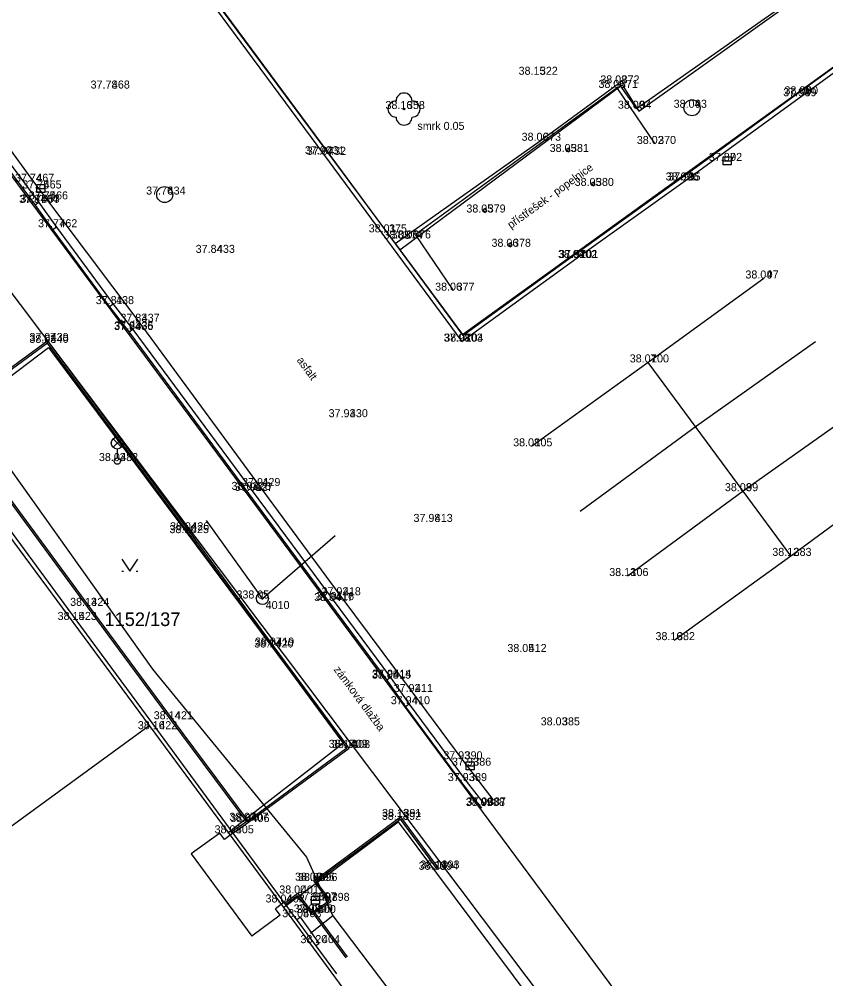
# Model space of a CAD drawing. Extents: x -609709 to -609357, y -1051535 to -1051131.
# Drawn here: x -609555.38 to -609530.2, y -1051361.09 to -1051331.13 of the extents above; entities that cross this region are included whole.
import ezdxf

# ---------------------------------------------------------------- set-up
doc = ezdxf.new("R2010")
doc.units = 0
for name, color, linetype in [('Vrstva 1', 7, 'Continuous'), ('Vrstva 10', 7, 'Continuous'), ('Vrstva 12', 7, 'Continuous'), ('Vrstva 18', 7, 'Continuous'), ('Vrstva 2', 7, 'Continuous'), ('Vrstva 3', 7, 'Continuous'), ('Vrstva 4', 7, 'Continuous'), ('Vrstva 5', 7, 'Continuous'), ('Vrstva 7', 7, 'Continuous'), ('Vrstva 9', 7, 'Continuous')]:
    doc.layers.add(name, color=color, linetype=linetype)

msp = doc.modelspace()

# ---------------------------------------------------------------- linework, layer by layer
at = {"layer": 'Vrstva 1'}
for p, q in [((-609539.22, -1051332.87), (-609539.22, -1051332.87)), ((-609552.58, -1051333.3), (-609552.58, -1051333.3)), ((-609536.72, -1051333.28), (-609536.72, -1051333.28)), ((-609536.67, -1051333.14), (-609536.67, -1051333.14)), ((-609530.96, -1051333.54), (-609530.96, -1051333.54)), ((-609530.91, -1051333.48), (-609530.91, -1051333.48)), ((-609534.38, -1051333.9), (-609534.38, -1051333.9)), ((-609543.37, -1051333.94), (-609543.37, -1051333.94)), ((-609536.11, -1051333.93), (-609536.11, -1051333.93)), ((-609539.12, -1051334.93), (-609539.12, -1051334.93)), ((-609535.53, -1051335.03), (-609535.53, -1051335.03)), ((-609545.88, -1051335.35), (-609545.88, -1051335.35)), ((-609545.83, -1051335.37), (-609545.83, -1051335.37)), ((-609538.25, -1051335.28), (-609538.25, -1051335.28)), ((-609533.28, -1051335.56), (-609533.28, -1051335.56)), ((-609554.94, -1051336.21), (-609554.94, -1051336.21)), ((-609534.63, -1051336.17), (-609534.63, -1051336.17)), ((-609534.58, -1051336.17), (-609534.58, -1051336.17)), ((-609554.71, -1051336.42), (-609554.71, -1051336.42)), ((-609550.84, -1051336.61), (-609550.84, -1051336.61)), ((-609537.47, -1051336.34), (-609537.47, -1051336.34)), ((-609554.81, -1051336.87), (-609554.81, -1051336.87)), ((-609554.77, -1051336.86), (-609554.77, -1051336.86)), ((-609554.51, -1051336.76), (-609554.51, -1051336.76)), ((-609540.85, -1051337.17), (-609540.85, -1051337.17)), ((-609554.22, -1051337.63), (-609554.22, -1051337.63)), ((-609543.93, -1051337.79), (-609543.93, -1051337.79)), ((-609543.44, -1051337.99), (-609543.44, -1051337.99)), ((-609543.18, -1051337.98), (-609543.18, -1051337.98)), ((-609540.06, -1051338.24), (-609540.06, -1051338.24)), ((-609549.3, -1051338.43), (-609549.3, -1051338.43)), ((-609537.99, -1051338.59), (-609537.99, -1051338.59)), ((-609537.96, -1051338.59), (-609537.96, -1051338.59)), ((-609532.14, -1051339.23), (-609532.14, -1051339.23)), ((-609541.82, -1051339.61), (-609541.82, -1051339.61)), ((-609552.45, -1051340.03), (-609552.45, -1051340.03)), ((-609551.65, -1051340.58), (-609551.65, -1051340.58)), ((-609551.85, -1051340.84), (-609551.85, -1051340.84)), ((-609551.84, -1051340.82), (-609551.84, -1051340.82)), ((-609554.49, -1051341.18), (-609554.49, -1051341.18)), ((-609554.49, -1051341.24), (-609554.49, -1051341.24)), ((-609541.56, -1051341.2), (-609541.56, -1051341.2)), ((-609541.54, -1051341.2), (-609541.54, -1051341.2)), ((-609535.75, -1051341.85), (-609535.75, -1051341.85)), ((-609545.15, -1051343.56), (-609545.15, -1051343.56)), ((-609539.39, -1051344.47), (-609539.39, -1051344.47)), ((-609552.32, -1051344.93), (-609552.32, -1051344.93)), ((-609548.18, -1051345.83), (-609548.18, -1051345.83)), ((-609548.11, -1051345.86), (-609548.11, -1051345.86)), ((-609547.88, -1051345.71), (-609547.88, -1051345.71)), ((-609532.78, -1051345.87), (-609532.78, -1051345.87)), ((-609550.1, -1051347.09), (-609550.1, -1051347.09)), ((-609542.5, -1051346.83), (-609542.5, -1051346.83)), ((-609550.11, -1051347.18), (-609550.11, -1051347.18)), ((-609531.3, -1051347.89), (-609531.3, -1051347.89)), ((-609536.39, -1051348.52), (-609536.39, -1051348.52)), ((-609545.37, -1051349.12), (-609545.37, -1051349.12)), ((-609553.22, -1051349.45), (-609553.22, -1051349.45)), ((-609547.79, -1051349.22), (-609547.79, -1051349.22)), ((-609545.6, -1051349.3), (-609545.6, -1051349.3)), ((-609545.58, -1051349.27), (-609545.58, -1051349.27)), ((-609553.61, -1051349.89), (-609553.61, -1051349.89)), ((-609547.45, -1051350.69), (-609547.45, -1051350.69)), ((-609534.94, -1051350.52), (-609534.94, -1051350.52)), ((-609547.47, -1051350.75), (-609547.47, -1051350.75)), ((-609539.57, -1051350.89), (-609539.57, -1051350.89)), ((-609543.8, -1051351.72), (-609543.8, -1051351.72)), ((-609543.79, -1051351.69), (-609543.79, -1051351.69)), ((-609543.12, -1051352.14), (-609543.12, -1051352.14)), ((-609543.21, -1051352.52), (-609543.21, -1051352.52)), ((-609550.61, -1051352.99), (-609550.61, -1051352.99)), ((-609551.1, -1051353.3), (-609551.1, -1051353.3)), ((-609538.53, -1051353.18), (-609538.53, -1051353.18)), ((-609545.15, -1051353.88), (-609545.15, -1051353.88)), ((-609545.08, -1051353.89), (-609545.08, -1051353.89)), ((-609541.57, -1051354.24), (-609541.57, -1051354.24)), ((-609541.3, -1051354.44), (-609541.3, -1051354.44)), ((-609541.43, -1051354.92), (-609541.43, -1051354.92)), ((-609540.87, -1051355.7), (-609540.87, -1051355.7)), ((-609540.84, -1051355.68), (-609540.84, -1051355.68)), ((-609543.48, -1051356.04), (-609543.48, -1051356.04)), ((-609548.25, -1051356.16), (-609548.25, -1051356.16)), ((-609548.22, -1051356.2), (-609548.22, -1051356.2)), ((-609543.49, -1051356.13), (-609543.49, -1051356.13)), ((-609548.71, -1051356.55), (-609548.71, -1051356.55)), ((-609542.33, -1051357.69), (-609542.33, -1051357.69)), ((-609542.29, -1051357.65), (-609542.29, -1051357.65)), ((-609546.19, -1051358.03), (-609546.19, -1051358.03)), ((-609546.1, -1051358.04), (-609546.1, -1051358.04)), ((-609546.68, -1051358.43), (-609546.68, -1051358.43)), ((-609547.12, -1051358.71), (-609547.12, -1051358.71)), ((-609546.13, -1051358.64), (-609546.13, -1051358.64)), ((-609545.72, -1051358.66), (-609545.72, -1051358.66)), ((-609546.24, -1051359.02), (-609546.24, -1051359.02)), ((-609546.15, -1051359.04), (-609546.15, -1051359.04)), ((-609546.6, -1051359.17), (-609546.6, -1051359.17)), ((-609546.02, -1051359.98), (-609546.02, -1051359.98))]:
    msp.add_line(p, q, dxfattribs=at)
at = {"layer": 'Vrstva 10'}
for p, q in [((-609581.79, -1051300.71), (-609506.66, -1051402.14)), ((-609567.21, -1051306.38), (-609543.5, -1051338.34)), ((-609541.54, -1051340.98), (-609507.4, -1051316.31)), ((-609536.04, -1051334.01), (-609523.24, -1051324.85)), ((-609543.5, -1051338.34), (-609536.56, -1051333.18)), ((-609536.56, -1051333.18), (-609536.04, -1051334.01)), ((-609543.5, -1051338.34), (-609541.54, -1051340.98)), ((-609558.05, -1051344.09), (-609554.47, -1051341.38)), ((-609554.47, -1051341.38), (-609545.26, -1051353.73)), ((-609558.05, -1051344.09), (-609551.33, -1051353.19)), ((-609552.18, -1051347.995), (-609551.93, -1051348.37)), ((-609551.93, -1051348.37), (-609551.68, -1051347.995)), ((-609552.18, -1051348.37), (-609552.13, -1051348.37)), ((-609551.73, -1051348.37), (-609551.68, -1051348.37)), ((-609560.47, -1051359.86), (-609551.33, -1051353.19)), ((-609551.33, -1051353.19), (-609548.86, -1051356.53)), ((-609548.86, -1051356.53), (-609545.26, -1051353.73)), ((-609547.13, -1051358.87), (-609543.55, -1051356.19)), ((-609543.55, -1051356.19), (-609530.27, -1051373.99)), ((-609548.86, -1051356.53), (-609547.13, -1051358.87)), ((-609547.13, -1051358.87), (-609540.48, -1051367.88))]:
    msp.add_line(p, q, dxfattribs=at)
at = {"layer": 'Vrstva 12'}
for points in [[(-609615.546, -1051325.052), (-609614.108, -1051326.974), (-609589.099, -1051308.266), (-609582.815, -1051303.565), (-609514.844, -1051393.856), (-609499.807, -1051382.785), (-609467.693, -1051377.467)], [(-609556.47, -1051344.07), (-609551.22, -1051351.43), (-609546.41, -1051357.3), (-609545.59, -1051359.13), (-609546.284, -1051359.683)], [(-609545.59, -1051359.13), (-609538.86, -1051368.03), (-609535.11, -1051373.63), (-609535.613, -1051374.09)]]:
    msp.add_lwpolyline(points, dxfattribs=at)
at = {"layer": 'Vrstva 18'}
for points in [[(-609547.79, -1051349.22), (-609549.537, -1051346.781)], [(-609547.79, -1051349.22), (-609545.52, -1051347.258)]]:
    msp.add_lwpolyline(points, dxfattribs=at)
for radius in [0.188, 0.025]:
    msp.add_circle((-609547.79, -1051349.22), radius, dxfattribs=at)
at = {"layer": 'Vrstva 4'}
for p, q in [((-609549.148, -1051330.697), (-609545.767, -1051335.267)), ((-609534.662, -1051336.056), (-609531.042, -1051333.427)), ((-609545.767, -1051335.267), (-609541.53, -1051341.005)), ((-609538.042, -1051338.476), (-609534.662, -1051336.056)), ((-609541.53, -1051341.005), (-609538.042, -1051338.476)), ((-609548.25, -1051356.16), (-609545.15, -1051353.879)), ((-609546.69, -1051358.5), (-609547.07, -1051358.779)), ((-609546.202, -1051359.054), (-609545.186, -1051360.435))]:
    msp.add_line(p, q, dxfattribs=at)
for points in [[(-609549.76, -1051288.75), (-609547.85, -1051291.29), (-609545.93, -1051293.92), (-609544.38, -1051296.08), (-609541.25, -1051300.29), (-609539.34, -1051302.91), (-609536.37, -1051306.73), (-609533.41, -1051311.01), (-609529.82, -1051315.81), (-609526.99, -1051319.64), (-609524.14, -1051323.52), (-609523.26, -1051324.77), (-609525.66, -1051326.48), (-609528.98, -1051328.94), (-609532.13, -1051331.13), (-609536.11, -1051333.93)], [(-609581.29, -1051300.49), (-609578.2, -1051304.72), (-609575.96, -1051307.74), (-609573.15, -1051311.54), (-609570.93, -1051314.56), (-609567.02, -1051319.88), (-609560.65, -1051328.46), (-609558.43, -1051331.45), (-609556.52, -1051334.05), (-609554.94, -1051336.21), (-609551.65, -1051340.58), (-609547.88, -1051345.71), (-609545.37, -1051349.12), (-609543.12, -1051352.14), (-609541.57, -1051354.24), (-609540.598, -1051355.492)], [(-609567.69, -1051305.73), (-609565.19, -1051309.21), (-609561.45, -1051314.29), (-609556.48, -1051321.05), (-609552.89, -1051325.9), (-609549.26, -1051330.78), (-609545.88, -1051335.35), (-609541.56, -1051341.2), (-609537.96, -1051338.59), (-609534.58, -1051336.17), (-609530.96, -1051333.54), (-609527.42, -1051330.97), (-609523.72, -1051328.34), (-609521.12, -1051326.49), (-609517.15, -1051323.61), (-609513.51, -1051320.93), (-609509.43, -1051317.99)], [(-609531.042, -1051333.427), (-609527.502, -1051330.856), (-609523.801, -1051328.226)], [(-609560.734, -1051329.062), (-609558.952, -1051331.474), (-609558.362, -1051332.244), (-609556.683, -1051334.523), (-609554.883, -1051336.942), (-609554.333, -1051337.712), (-609552.562, -1051340.114), (-609551.952, -1051340.904), (-609548.222, -1051345.943), (-609545.692, -1051349.353), (-609543.904, -1051351.772), (-609543.324, -1051352.602), (-609541.542, -1051355.005), (-609540.951, -1051355.766)], [(-609560.62, -1051328.98), (-609558.84, -1051331.39), (-609558.25, -1051332.16), (-609556.57, -1051334.44), (-609554.77, -1051336.86), (-609554.22, -1051337.63), (-609552.45, -1051340.03), (-609551.84, -1051340.82), (-609548.11, -1051345.86), (-609545.58, -1051349.27), (-609543.79, -1051351.69), (-609543.21, -1051352.52), (-609541.43, -1051354.92), (-609540.84, -1051355.68)], [(-609543.648, -1051338.137), (-609539.12, -1051334.93), (-609536.67, -1051333.14)], [(-609536.67, -1051333.14), (-609536.11, -1051333.93)], [(-609554.77, -1051336.86), (-609554.883, -1051336.942)], [(-609554.22, -1051337.63), (-609554.333, -1051337.712)], [(-609532.14, -1051339.23), (-609535.75, -1051341.85), (-609539.39, -1051344.47)], [(-609552.45, -1051340.03), (-609552.562, -1051340.114)], [(-609551.84, -1051340.82), (-609551.952, -1051340.904)], [(-609545.08, -1051353.89), (-609547.45, -1051350.69), (-609550.1, -1051347.09), (-609554.49, -1051341.18), (-609557.62, -1051343.47)], [(-609545.15, -1051353.879), (-609547.49, -1051350.72), (-609550.14, -1051347.12), (-609554.501, -1051341.25), (-609557.59, -1051343.51)], [(-609530.525, -1051341.21), (-609534.242, -1051343.842), (-609537.869, -1051346.505)], [(-609531.3, -1051347.89), (-609532.78, -1051345.87), (-609535.75, -1051341.85)], [(-609529.08, -1051343.25), (-609532.78, -1051345.87), (-609536.39, -1051348.52)], [(-609557.635, -1051343.543), (-609557.04, -1051344.35), (-609553.26, -1051349.48), (-609550.65, -1051353.02), (-609548.291, -1051356.189)], [(-609557.595, -1051343.514), (-609557, -1051344.32), (-609553.22, -1051349.45), (-609550.61, -1051352.99), (-609548.25, -1051356.16)], [(-609534.94, -1051350.52), (-609531.3, -1051347.89), (-609527.68, -1051345.23)], [(-609543.79, -1051351.69), (-609543.904, -1051351.772)], [(-609543.21, -1051352.52), (-609543.324, -1051352.602)], [(-609548.22, -1051356.2), (-609545.08, -1051353.89)], [(-609546.68, -1051358.43), (-609546.24, -1051359.02), (-609545.72, -1051358.66), (-609546.19, -1051358.03), (-609543.48, -1051356.04), (-609542.29, -1051357.65)], [(-609548.25, -1051356.16), (-609548.74, -1051356.51)], [(-609548.71, -1051356.55), (-609548.22, -1051356.2)], [(-609546.69, -1051358.5), (-609546.251, -1051359.089), (-609545.649, -1051358.672), (-609546.12, -1051358.04), (-609543.491, -1051356.11), (-609542.33, -1051357.68)], [(-609546.68, -1051358.43), (-609547.099, -1051358.738)], [(-609546.16, -1051359.026), (-609545.146, -1051360.406)]]:
    msp.add_lwpolyline(points, dxfattribs=at)
at = {"layer": 'Vrstva 5'}
for p, q in [((-609533.405, -1051335.56), (-609533.155, -1051335.56)), ((-609554.835, -1051336.42), (-609554.585, -1051336.42)), ((-609552.453, -1051344.5), (-609552.188, -1051344.235)), ((-609552.453, -1051344.235), (-609552.188, -1051344.5)), ((-609552.32, -1051344.555), (-609552.32, -1051344.83)), ((-609541.425, -1051354.44), (-609541.175, -1051354.44)), ((-609546.255, -1051358.64), (-609546.005, -1051358.64))]:
    msp.add_line(p, q, dxfattribs=at)
for points in [[(-609535.53, -1051335.03), (-609536.72, -1051333.28), (-609543.012, -1051337.858)], [(-609538.25, -1051335.28), (-609538.186, -1051335.232), (-609538.239, -1051335.16), (-609538.303, -1051335.208)], [(-609538.303, -1051335.208), (-609538.25, -1051335.28)], [(-609537.47, -1051336.34), (-609537.406, -1051336.292), (-609537.459, -1051336.22), (-609537.523, -1051336.268)], [(-609537.523, -1051336.268), (-609537.47, -1051336.34)], [(-609540.85, -1051337.17), (-609540.786, -1051337.122), (-609540.839, -1051337.05), (-609540.903, -1051337.098)], [(-609540.903, -1051337.098), (-609540.85, -1051337.17)], [(-609541.82, -1051339.61), (-609543.012, -1051337.858)], [(-609540.06, -1051338.24), (-609539.996, -1051338.192), (-609540.049, -1051338.12), (-609540.113, -1051338.168)], [(-609540.113, -1051338.168), (-609540.06, -1051338.24)]]:
    msp.add_lwpolyline(points, dxfattribs=at)
for points in [[(-609533.405, -1051335.435), (-609533.155, -1051335.435), (-609533.155, -1051335.685), (-609533.405, -1051335.685)], [(-609554.835, -1051336.295), (-609554.585, -1051336.295), (-609554.585, -1051336.545), (-609554.835, -1051336.545)], [(-609541.425, -1051354.315), (-609541.175, -1051354.315), (-609541.175, -1051354.565), (-609541.425, -1051354.565)], [(-609546.255, -1051358.515), (-609546.005, -1051358.515), (-609546.005, -1051358.765), (-609546.255, -1051358.765)]]:
    msp.add_lwpolyline(points, close=True, dxfattribs=at)
for centre, radius in [((-609534.38, -1051333.9), 0.25), ((-609550.84, -1051336.61), 0.25), ((-609552.32, -1051344.367), 0.188), ((-609552.32, -1051344.93), 0.1)]:
    msp.add_circle(centre, radius, dxfattribs=at)
at = {"layer": 'Vrstva 7'}
msp.add_circle((-609543.37, -1051333.94), 0.025, dxfattribs=at)
for centre, start, end in [((-609543.37, -1051333.69), 0, 180), ((-609543.62, -1051333.94), 90, 270), ((-609543.12, -1051333.94), 270, 90), ((-609543.37, -1051334.19), 180, 0)]:
    msp.add_arc(centre, 0.25, start, end, dxfattribs=at)
at = {"layer": 'Vrstva 9'}
for points in [[(-609558.09, -1051343.81), (-609553.61, -1051349.89), (-609551.1, -1051353.3), (-609548.71, -1051356.55)], [(-609549.124, -1051356.544), (-609550.01, -1051357.196)], [(-609548.976, -1051356.746), (-609549.124, -1051356.544)], [(-609548.71, -1051356.55), (-609548.976, -1051356.746)], [(-609548.71, -1051356.55), (-609547.12, -1051358.71)], [(-609550.01, -1051357.196), (-609548.124, -1051359.759)], [(-609547.12, -1051358.71), (-609547.386, -1051358.906)], [(-609547.12, -1051358.71), (-609545.479, -1051360.942)], [(-609547.238, -1051359.107), (-609547.386, -1051358.906)], [(-609547.238, -1051359.107), (-609548.124, -1051359.759)], [(-609546.128, -1051360.059), (-609546.02, -1051359.98), (-609546.6, -1051359.17), (-609546.718, -1051359.257)]]:
    msp.add_lwpolyline(points, dxfattribs=at)

# ---------------------------------------------------------------- texts
at = {"layer": 'Vrstva 10'}
msp.add_text('1152/137', height=0.425, dxfattribs=at).set_placement((-609552.72, -1051350.08))
at = {"layer": 'Vrstva 18'}
msp.add_text(' 4010', height=0.25, dxfattribs=at).set_placement((-609547.78, -1051349.55))
at = {"layer": 'Vrstva 2'}
for s, p in [(' 322', (-609539.22, -1051332.87)), (' 372', (-609536.67, -1051333.14)), (' 468', (-609552.58, -1051333.3)), (' 371', (-609536.72, -1051333.28)), (' 89', (-609530.96, -1051333.54)), (' 90', (-609530.91, -1051333.48)), (' 358', (-609543.37, -1051333.94)), (' 94', (-609536.11, -1051333.93)), (' 93', (-609534.38, -1051333.9)), (' 373', (-609539.12, -1051334.93)), (' 370', (-609535.53, -1051335.03)), (' 431', (-609545.88, -1051335.35)), (' 432', (-609545.83, -1051335.37)), (' 381', (-609538.25, -1051335.28)), (' 92', (-609533.28, -1051335.56)), (' 467', (-609554.94, -1051336.21)), (' 96', (-609534.63, -1051336.17)), (' 95', (-609534.58, -1051336.17)), (' 465', (-609554.71, -1051336.42)), (' 380', (-609537.47, -1051336.34)), (' 464', (-609554.81, -1051336.87)), (' 463', (-609554.77, -1051336.86)), (' 466', (-609554.51, -1051336.76)), (' 434', (-609550.84, -1051336.61)), (' 379', (-609540.85, -1051337.17)), (' 462', (-609554.22, -1051337.63)), (' 375', (-609543.93, -1051337.79)), (' 374', (-609543.44, -1051337.99)), (' 376', (-609543.18, -1051337.98)), (' 378', (-609540.06, -1051338.24)), (' 433', (-609549.3, -1051338.43)), (' 102', (-609537.99, -1051338.59)), (' 101', (-609537.96, -1051338.59)), (' 97', (-609532.14, -1051339.23)), (' 377', (-609541.82, -1051339.61)), (' 438', (-609552.45, -1051340.03)), (' 437', (-609551.65, -1051340.58)), (' 436', (-609551.85, -1051340.84)), (' 435', (-609551.84, -1051340.82)), (' 439', (-609554.49, -1051341.18)), (' 440', (-609554.49, -1051341.24)), (' 103', (-609541.56, -1051341.2)), (' 104', (-609541.54, -1051341.2)), (' 100', (-609535.75, -1051341.85)), (' 430', (-609545.15, -1051343.56)), (' 105', (-609539.39, -1051344.47)), (' 482', (-609552.32, -1051344.93)), (' 428', (-609548.18, -1051345.83)), (' 427', (-609548.11, -1051345.86)), (' 429', (-609547.88, -1051345.71)), (' 99', (-609532.78, -1051345.87)), (' 413', (-609542.5, -1051346.83)), (' 425', (-609550.11, -1051347.18)), (' 426', (-609550.1, -1051347.09)), (' 383', (-609531.3, -1051347.89)), (' 106', (-609536.39, -1051348.52)), (' 418', (-609545.37, -1051349.12)), (' 424', (-609553.22, -1051349.45)), (' 417', (-609545.6, -1051349.3)), (' 416', (-609545.58, -1051349.27)), (' 423', (-609553.61, -1051349.89)), (' 382', (-609534.94, -1051350.52)), (' 420', (-609547.47, -1051350.75)), (' 419', (-609547.45, -1051350.69)), (' 412', (-609539.57, -1051350.89)), (' 415', (-609543.8, -1051351.72)), (' 414', (-609543.79, -1051351.69)), (' 411', (-609543.12, -1051352.14)), (' 410', (-609543.21, -1051352.52)), (' 421', (-609550.61, -1051352.99)), (' 422', (-609551.1, -1051353.3)), (' 385', (-609538.53, -1051353.18)), (' 409', (-609545.15, -1051353.88)), (' 408', (-609545.08, -1051353.89)), (' 390', (-609541.57, -1051354.24)), (' 386', (-609541.3, -1051354.44)), (' 389', (-609541.43, -1051354.92)), (' 388', (-609540.87, -1051355.7)), (' 387', (-609540.84, -1051355.68)), (' 391', (-609543.48, -1051356.04)), (' 407', (-609548.25, -1051356.16)), (' 406', (-609548.22, -1051356.2)), (' 392', (-609543.49, -1051356.13)), (' 405', (-609548.71, -1051356.55)), (' 394', (-609542.33, -1051357.69)), (' 393', (-609542.29, -1051357.65)), (' 395', (-609546.19, -1051358.03)), (' 396', (-609546.1, -1051358.04)), (' 401', (-609546.68, -1051358.43)), (' 402', (-609547.12, -1051358.71)), (' 397', (-609546.13, -1051358.64)), (' 398', (-609545.72, -1051358.66)), (' 399', (-609546.24, -1051359.02)), (' 400', (-609546.15, -1051359.04)), (' 403', (-609546.6, -1051359.17)), (' 404', (-609546.02, -1051359.98))]:
    msp.add_text(s, height=0.25, dxfattribs=at).set_placement(p)
at = {"layer": 'Vrstva 3'}
for s, p in [('38.15', (-609539.793, -1051332.87)), ('38.08', (-609537.243, -1051333.14)), ('37.78', (-609553.153, -1051333.3)), ('38.06', (-609537.299, -1051333.28)), ('37.94', (-609531.533, -1051333.54)), ('38.00', (-609531.493, -1051333.48)), ('38.16', (-609543.949, -1051333.94)), ('38.00', (-609536.693, -1051333.93)), ('38.04', (-609534.953, -1051333.9)), ('38.06', (-609539.699, -1051334.93)), ('38.02', (-609536.103, -1051335.03)), ('37.90', (-609546.463, -1051335.35)), ('37.97', (-609546.403, -1051335.37)), ('38.05', (-609538.823, -1051335.28)), ('37.87', (-609533.853, -1051335.56)), ('37.74', (-609555.513, -1051336.21)), ('38.02', (-609535.203, -1051336.17)), ('37.91', (-609535.122, -1051336.17)), ('37.75', (-609555.283, -1051336.42)), ('38.05', (-609538.043, -1051336.34)), ('37.87', (-609555.383, -1051336.87)), ('37.75', (-609555.343, -1051336.86)), ('37.75', (-609555.083, -1051336.76)), ('37.76', (-609551.419, -1051336.61)), ('38.05', (-609541.423, -1051337.17)), ('37.77', (-609554.793, -1051337.63)), ('38.01', (-609544.472, -1051337.79)), ('38.05', (-609544.013, -1051337.99)), ('38.06', (-609543.759, -1051337.98)), ('38.06', (-609540.639, -1051338.24)), ('37.84', (-609549.873, -1051338.43)), ('38.04', (-609538.563, -1051338.59)), ('37.97', (-609538.533, -1051338.59)), ('38.04', (-609532.713, -1051339.23)), ('38.06', (-609542.399, -1051339.61)), ('37.81', (-609552.992, -1051340.03)), ('37.83', (-609552.223, -1051340.58)), ('37.94', (-609552.423, -1051340.84)), ('37.83', (-609552.413, -1051340.82)), ('37.97', (-609555.063, -1051341.18)), ('38.03', (-609555.063, -1051341.24)), ('37.98', (-609542.133, -1051341.2)), ('38.07', (-609542.113, -1051341.2)), ('38.07', (-609536.323, -1051341.85)), ('37.93', (-609545.723, -1051343.56)), ('38.08', (-609539.963, -1051344.47)), ('38.03', (-609552.893, -1051344.93)), ('38.02', (-609548.753, -1051345.83)), ('37.91', (-609548.652, -1051345.86)), ('37.91', (-609548.422, -1051345.71)), ('38.08', (-609533.353, -1051345.87)), ('37.98', (-609543.073, -1051346.83)), ('38.10', (-609550.693, -1051347.18)), ('38.04', (-609550.673, -1051347.09)), ('38.12', (-609531.873, -1051347.89)), ('38.13', (-609536.963, -1051348.52)), ('37.92', (-609545.943, -1051349.12)), ('38.13', (-609553.793, -1051349.45)), ('338.05', (-609548.6, -1051349.22)), ('38.04', (-609546.173, -1051349.3)), ('37.91', (-609546.122, -1051349.27)), ('38.15', (-609554.183, -1051349.89)), ('38.16', (-609535.519, -1051350.52)), ('38.14', (-609548.043, -1051350.75)), ('38.07', (-609548.023, -1051350.69)), ('38.05', (-609540.143, -1051350.89)), ('38.05', (-609544.373, -1051351.72)), ('37.94', (-609544.363, -1051351.69)), ('37.92', (-609543.693, -1051352.14)), ('37.94', (-609543.783, -1051352.52)), ('38.14', (-609551.183, -1051352.99)), ('38.16', (-609551.679, -1051353.3)), ('38.03', (-609539.103, -1051353.18)), ('38.17', (-609545.723, -1051353.88)), ('38.11', (-609545.622, -1051353.89)), ('37.93', (-609542.143, -1051354.24)), ('37.93', (-609541.873, -1051354.44)), ('37.93', (-609542.003, -1051354.92)), ('38.09', (-609541.443, -1051355.7)), ('37.96', (-609541.419, -1051355.68)), ('38.12', (-609544.053, -1051356.04)), ('38.07', (-609548.823, -1051356.16)), ('38.04', (-609548.793, -1051356.2)), ('38.18', (-609544.063, -1051356.13)), ('38.03', (-609549.283, -1051356.55)), ('38.20', (-609542.913, -1051357.69)), ('38.14', (-609542.863, -1051357.65)), ('38.00', (-609546.773, -1051358.03)), ('38.06', (-609546.679, -1051358.04)), ('38.00', (-609547.263, -1051358.43)), ('38.04', (-609547.693, -1051358.71)), ('37.98', (-609546.703, -1051358.64)), ('37.97', (-609546.293, -1051358.66)), ('37.98', (-609546.813, -1051359.02)), ('38.03', (-609546.723, -1051359.04)), ('38.05', (-609547.173, -1051359.17)), ('38.20', (-609546.603, -1051359.98))]:
    msp.add_text(s, height=0.25, dxfattribs=at).set_placement(p)
at = {"layer": 'Vrstva 4'}
for s, rotation, p in [('asfalt', 306.3119, (-609546.731, -1051341.786)), ('zámková dlažba', 306.5246, (-609545.578, -1051351.443))]:
    msp.add_text(s, height=0.25, rotation=rotation, dxfattribs=at).set_placement(p)
at = {"layer": 'Vrstva 5'}
msp.add_text('přístřešek - popelnice', height=0.25, rotation=35.8524, dxfattribs=at).set_placement((-609540.032, -1051337.688))
at = {"layer": 'Vrstva 7'}
msp.add_text('smrk 0.05', height=0.25, dxfattribs=at).set_placement((-609542.95, -1051334.59))

doc.saveas('drawing.dxf')
